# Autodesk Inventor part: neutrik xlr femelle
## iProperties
Created: 2011-01
Part Number: neutrik xlr femelle
Document SubType Name: Modeling
Designer: eric
Density: 1 g/cm^3
Mass: 9.17712 g
Surface Area: 63.9956 cm^2
Volume: 9.17712 cm^3
Author: eric
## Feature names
1. Base1
